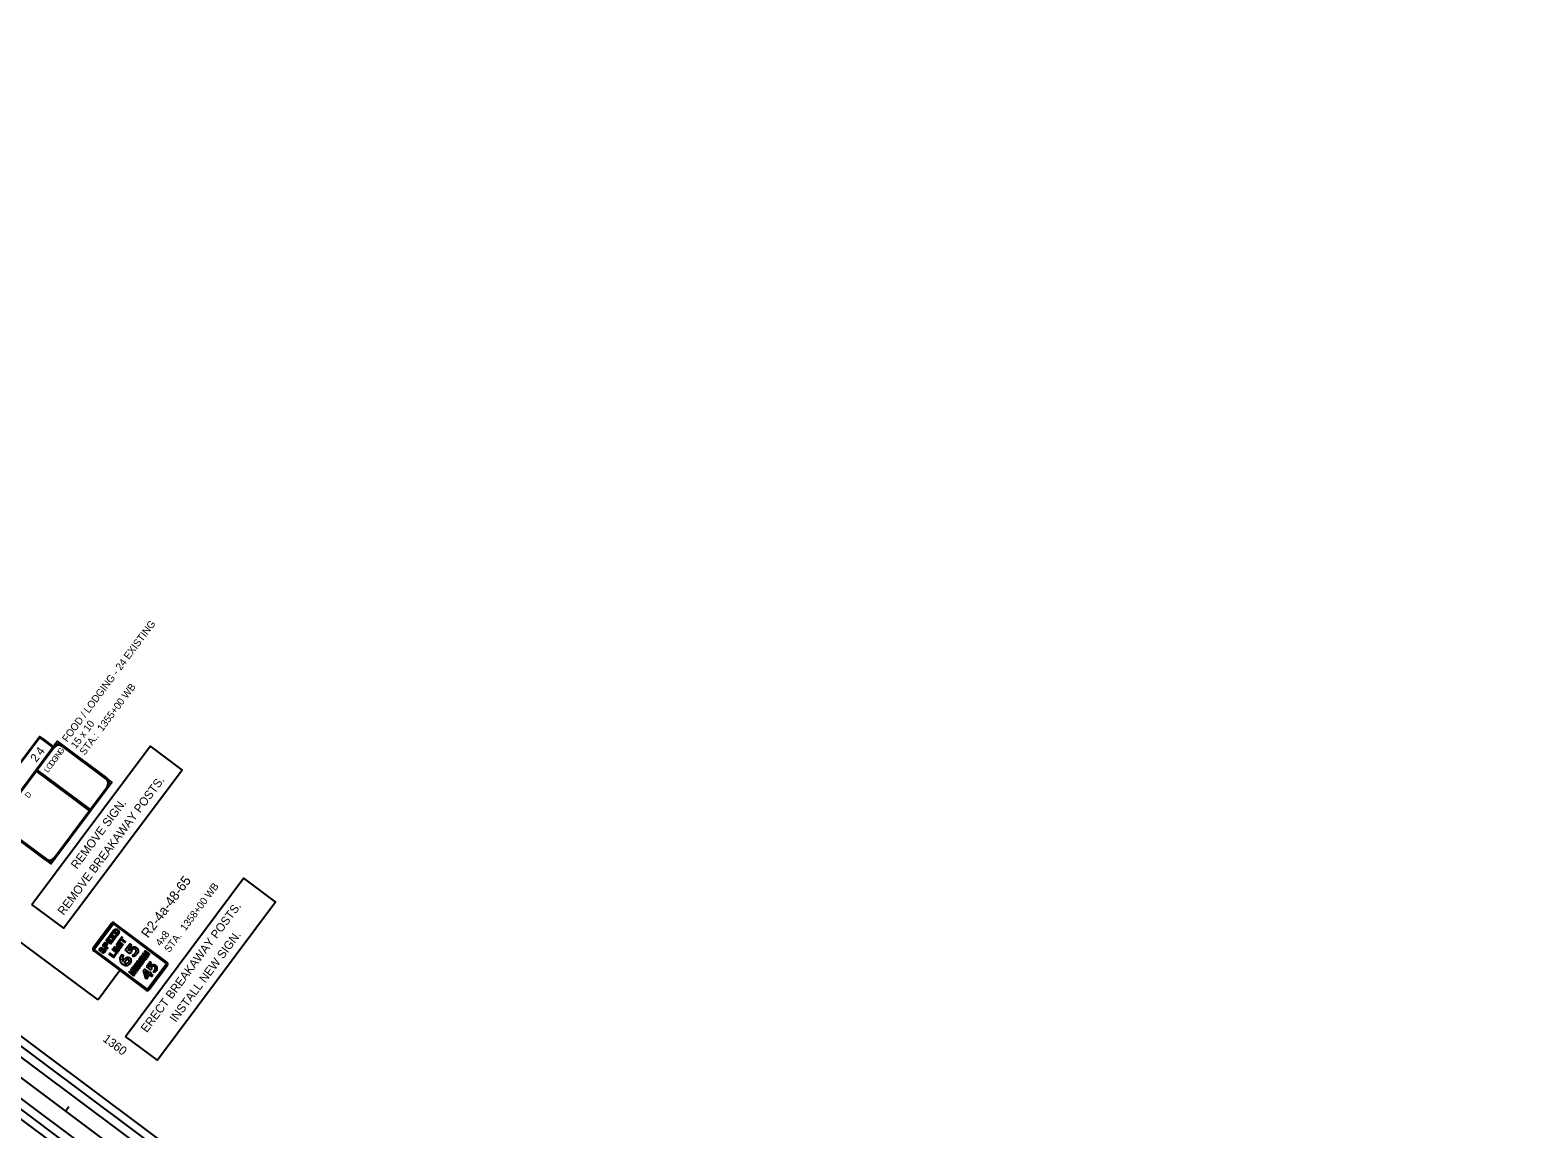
# Model space of a CAD drawing. Extents: x 2338610 to 2351914, y 366540 to 376484.
# Drawn here: x 2343223 to 2345299, y 372032 to 373544 of the extents above; entities that cross this region are included whole.
import ezdxf

# ---------------------------------------------------------------- set-up
doc = ezdxf.new("R2010")
doc.units = 0
for name, color, linetype in [('RD_HC_Cl', 7, 'Continuous'), ('RD_PD_Final_LnLine', 7, 'Continuous'), ('RD_PD_Final_TrvlWay', 7, 'Continuous'), ('TR PM PAVEMENT MARKING NOTES', 7, 'Continuous'), ('TR PM UNASSIGNED 3', 7, 'Continuous'), ('TR SN EXISTING - BREAK-AWAY SIGN SUPPORTS', 7, 'Continuous'), ('TR SN EXTRUDED PANEL SIGNS - GROUND MOUNTED', 7, 'Continuous'), ('TR SN FLAT SHEET - TYPE III - FIXED SZ and MSG SIGN', 7, 'Continuous'), ('TR SN UNASSIGNED 7', 7, 'Continuous')]:
    doc.layers.add(name, color=color, linetype=linetype)

msp = doc.modelspace()

# ---------------------------------------------------------------- linework, layer by layer
at = {"layer": 'RD_HC_Cl'}
msp.add_line((2339299.7, 375020.3), (2345298.7, 370542.8), dxfattribs=at)
at = {"layer": 'RD_PD_Final_LnLine'}
for p, q in [((2343504.5, 371925.7), (2339320.6, 375048.4)), ((2343497.3, 371916.1), (2339313.4, 375038.8)), ((2339278.7, 374992.3), (2343462.6, 371869.6)), ((2339285.9, 375001.9), (2343469.8, 371879.2))]:
    msp.add_line(p, q, dxfattribs=at)
at = {"layer": 'RD_PD_Final_TrvlWay'}
for p, q in [((2343458.6, 371973.7), (2339327.2, 375057.2)), ((2339272.2, 374983.5), (2343456.1, 371860.8))]:
    msp.add_line(p, q, dxfattribs=at)
at = {"layer": 'TR PM PAVEMENT MARKING NOTES'}
for p, q in [((2343334.7, 372314.4), (2343309.6, 372280.7)), ((2343335.3, 372313.9), (2343336.3, 372313.2)), ((2343337.7, 372313.4), (2343338.4, 372314.4)), ((2343411, 372261.2), (2343338.9, 372315)), ((2343311.2, 372279.5), (2343310.2, 372280.3)), ((2343310.2, 372276.5), (2343382.3, 372222.7)), ((2343310.6, 372277.1), (2343311.4, 372278.1)), ((2343386.5, 372223.3), (2343411.6, 372257)), ((2343410.6, 372260.5), (2343409.8, 372259.5)), ((2343410, 372258.1), (2343411, 372257.4)), ((2343383.5, 372224.3), (2343382.8, 372223.3)), ((2343385.9, 372223.7), (2343384.9, 372224.5))]:
    msp.add_line(p, q, dxfattribs=at)
for points in [[(2343335.3, 372313.9), (2343310.2, 372280.3), (2343311.2, 372279.5), (2343336.3, 372313.2), (2343335.3, 372313.9)], [(2343410.6, 372260.5), (2343338.4, 372314.4), (2343337.7, 372313.4), (2343409.8, 372259.5), (2343410.6, 372260.5)], [(2343310.6, 372277.1), (2343382.8, 372223.3), (2343383.5, 372224.3), (2343311.4, 372278.1), (2343310.6, 372277.1)], [(2343385.9, 372223.7), (2343411, 372257.4), (2343410, 372258.1), (2343384.9, 372224.5), (2343385.9, 372223.7)]]:
    msp.add_lwpolyline(points, close=True, dxfattribs=at)
for points in [[(2343322.1, 372284.2), (2343324.5, 372287.3)], [(2343325.6, 372286.5), (2343324, 372284.4)], [(2343337.3, 372291.1), (2343333.8, 372286.4), (2343327.4, 372291.2), (2343330.8, 372295.8), (2343331.9, 372295), (2343329.3, 372291.5), (2343330.6, 372290.5), (2343332, 372292.4), (2343333.1, 372291.6), (2343331.7, 372289.7), (2343333.5, 372288.3), (2343336.2, 372291.9), (2343337.3, 372291.1)], [(2343341.8, 372297.2), (2343338.3, 372292.5), (2343331.9, 372297.2), (2343335.3, 372301.9), (2343336.4, 372301), (2343333.8, 372297.5), (2343335.1, 372296.6), (2343336.5, 372298.5), (2343337.6, 372297.6), (2343336.2, 372295.7), (2343338, 372294.4), (2343340.7, 372298), (2343341.8, 372297.2)], [(2343336.3, 372303.1), (2343337.8, 372305.2)], [(2343344.2, 372300.4), (2343342.7, 372298.3), (2343336.3, 372303.1)], [(2343348.8, 372282.3), (2343348, 372281.2), (2343344.1, 372284.1), (2343346.6, 372279.3), (2343341.3, 372280.4), (2343345.2, 372277.4), (2343344.4, 372276.3), (2343338, 372281.1), (2343338.8, 372282.3), (2343344, 372281.2), (2343341.5, 372285.9), (2343342.4, 372287), (2343348.8, 372282.3)], [(2343338.9, 372304.4), (2343338.2, 372303.4)], [(2343338.2, 372303.4), (2343342.4, 372300.3), (2343343.1, 372301.2)], [(2343350.8, 372285), (2343350, 372283.9), (2343343.6, 372288.7), (2343344.4, 372289.8), (2343350.8, 372285)], [(2343349.9, 372295.1), (2343348.6, 372293.3), (2343354, 372289.2), (2343353.2, 372288.1), (2343347.8, 372292.2), (2343346.4, 372290.4), (2343345.4, 372291.1), (2343348.9, 372295.8), (2343349.9, 372295.1)], [(2343353.6, 372277.9), (2343359.9, 372286.3), (2343362.1, 372284.6), (2343357.4, 372278.3), (2343359.3, 372276.6)], [(2343320.8, 372277.5), (2343322.4, 372279)], [(2343321.5, 372281.5), (2343321.7, 372280.1)], [(2343323.3, 372278), (2343321.7, 372276.5)], [(2343328.4, 372284.4), (2343326.9, 372282.3), (2343329.4, 372280.5), (2343328.5, 372279.4), (2343322.1, 372284.2)], [(2343322.3, 372273.4), (2343322.3, 372274.8)], [(2343324, 372284.4), (2343325.8, 372283.2), (2343327.3, 372285.2)], [(2343341.3, 372272.3), (2343337.8, 372267.6), (2343331.4, 372272.3), (2343332.2, 372273.4), (2343337.6, 372269.4), (2343340.3, 372273), (2343341.3, 372272.3)], [(2343343.1, 372274.7), (2343342.3, 372273.6), (2343335.9, 372278.4), (2343336.7, 372279.5), (2343343.1, 372274.7)], [(2343348.7, 372271.3), (2343349.2, 372272)], [(2343349.2, 372272), (2343351.4, 372270.3), (2343351, 372269.7)], [(2343361.6, 372274.6), (2343359.3, 372273), (2343353.6, 372277.9)], [(2343364.8, 372268.3), (2343363.5, 372270.7)], [(2343379.5, 372261.5), (2343378.8, 372260.6), (2343375.2, 372263.3), (2343377.9, 372259.4), (2343373.4, 372260.9), (2343377, 372258.2), (2343376.4, 372257.3), (2343369.9, 372262.1), (2343370.6, 372263.1), (2343375, 372261.6), (2343372.4, 372265.4), (2343373, 372266.3), (2343379.5, 372261.5)], [(2343378.8, 372264.1), (2343374, 372267.6), (2343374.7, 372268.5), (2343379.5, 372265)], [(2343380.8, 372266.7), (2343376, 372270.2), (2343376.7, 372271.1)], [(2343376.7, 372271.1), (2343381.4, 372267.6)], [(2343387.2, 372271.9), (2343386.5, 372271), (2343382.9, 372273.7), (2343385.6, 372269.8), (2343381.2, 372271.3), (2343384.8, 372268.6), (2343384.1, 372267.7), (2343377.7, 372272.5), (2343378.4, 372273.4), (2343382.7, 372272), (2343380.1, 372275.7), (2343380.8, 372276.7), (2343387.2, 372271.9)], [(2343368.4, 372246.6), (2343367.7, 372245.7), (2343364.1, 372248.4), (2343366.8, 372244.6), (2343362.3, 372246.1), (2343365.9, 372243.4), (2343365.3, 372242.5), (2343358.8, 372247.3), (2343359.5, 372248.2), (2343363.9, 372246.7), (2343361.3, 372250.5), (2343361.9, 372251.4), (2343368.4, 372246.6)], [(2343370, 372248.9), (2343369.4, 372248), (2343363, 372252.8), (2343363.6, 372253.7), (2343370, 372248.9)], [(2343373.7, 372253.7), (2343373.1, 372253), (2343367.5, 372254.3), (2343371.7, 372251.1), (2343371, 372250.2), (2343364.6, 372255), (2343365.3, 372255.9), (2343370.3, 372254.8), (2343366.6, 372257.6), (2343367.3, 372258.5), (2343373.7, 372253.7)], [(2343375.3, 372256), (2343374.7, 372255.1), (2343368.3, 372259.9), (2343368.9, 372260.8), (2343375.3, 372256)], [(2343389.3, 372246.3), (2343388.5, 372245.3), (2343391.3, 372243.2), (2343390, 372241.4), (2343387.2, 372243.5), (2343383.2, 372238.1), (2343382.1, 372238.8), (2343378.8, 372249.8), (2343380.1, 372251.5), (2343387, 372246.4), (2343387.7, 372247.5), (2343389.3, 372246.3)], [(2343385.7, 372244.7), (2343381.5, 372247.8), (2343383.4, 372241.6), (2343385.7, 372244.7)], [(2343382.9, 372255.2), (2343387.6, 372261.6), (2343389.4, 372260.3), (2343385.9, 372255.6), (2343387.8, 372254)], [(2343390.2, 372251.9), (2343388.5, 372250.6), (2343382.9, 372255.2)], [(2343393.3, 372246.6), (2343392.3, 372248.5)]]:
    msp.add_lwpolyline(points, dxfattribs=at)
for centre, radius, start, end in [((2343337.1, 372312.6), 3, 53.2637, 143.2639), ((2343337.1, 372312.6), 2.25, 53.2637, 143.2639), ((2343337.1, 372312.6), 1, 53.2637, 143.2639), ((2343312, 372278.9), 3, 143.2639, 233.2636), ((2343312, 372278.9), 2.25, 143.2639, 233.2636), ((2343312, 372278.9), 1, 143.2639, 233.2636), ((2343409.2, 372258.7), 1, 323.2638, 53.264), ((2343409.2, 372258.7), 2.25, 323.2638, 53.264), ((2343409.2, 372258.7), 3, 323.2638, 53.264), ((2343384.1, 372225.1), 3, 233.2636, 323.2638), ((2343384.1, 372225.1), 2.25, 233.2636, 323.2638), ((2343384.1, 372225.1), 1, 233.2636, 323.2638)]:
    msp.add_arc(centre, radius, start, end, dxfattribs=at)
for points in [[(2343337.8, 372305.2), (2343338.7, 372306.3), (2343340.1, 372306.6), (2343341.5, 372306.9), (2343342.7, 372306.2), (2343343, 372306), (2343343.3, 372305.8), (2343343.6, 372305.6), (2343343.9, 372305.3), (2343344.9, 372304.3), (2343345, 372302.9), (2343345.1, 372301.5), (2343344.2, 372300.4)], [(2343324.5, 372287.3), (2343325.1, 372288.1), (2343326.1, 372288.3), (2343327.1, 372288.4), (2343327.9, 372287.8), (2343328.7, 372287.2), (2343328.8, 372286.2), (2343329, 372285.2), (2343328.4, 372284.4)], [(2343327.3, 372285.2), (2343327.5, 372285.6), (2343327.5, 372286), (2343327.4, 372286.4), (2343327.1, 372286.7), (2343326.7, 372287), (2343326.3, 372286.9), (2343325.8, 372286.8), (2343325.6, 372286.5)], [(2343343.1, 372301.2), (2343343.7, 372302), (2343343.6, 372302.9), (2343343.5, 372303.7), (2343342.9, 372304.4), (2343342.7, 372304.5), (2343342.5, 372304.7), (2343342.2, 372304.9), (2343342, 372305), (2343341.2, 372305.5), (2343340.3, 372305.3), (2343339.5, 372305.1), (2343338.9, 372304.4)], [(2343321.7, 372276.5), (2343321.1, 372276), (2343320.4, 372276), (2343319.6, 372275.9), (2343319, 372276.4), (2343318.5, 372276.8), (2343318.3, 372277.3), (2343318, 372277.9), (2343318.2, 372278.5), (2343318.4, 372279.3), (2343318.8, 372280), (2343319.8, 372281.3), (2343321.5, 372281.5)], [(2343321.7, 372280.1), (2343320.6, 372280), (2343319.9, 372279.2), (2343319.6, 372278.7), (2343319.5, 372278.3), (2343319.4, 372277.8), (2343319.8, 372277.5), (2343320, 372277.3), (2343320.3, 372277.3), (2343320.6, 372277.3), (2343320.8, 372277.5)], [(2343322.4, 372279), (2343323, 372279.5), (2343323.8, 372279.6), (2343324.6, 372279.6), (2343325.3, 372279.1), (2343326.4, 372278.3), (2343326.2, 372277), (2343326.1, 372275.9), (2343325.5, 372275), (2343324.9, 372274.3), (2343324, 372273.8), (2343323.2, 372273.4), (2343322.3, 372273.4)], [(2343322.3, 372274.8), (2343323.6, 372274.8), (2343324.4, 372275.9), (2343324.8, 372276.5), (2343324.9, 372277.2), (2343324.9, 372277.7), (2343324.5, 372278), (2343324.2, 372278.2), (2343323.9, 372278.2), (2343323.5, 372278.2), (2343323.3, 372278)], [(2343351, 372269.7), (2343349.6, 372267.9), (2343349.6, 372265.8), (2343349.5, 372263.6), (2343350.6, 372261.8), (2343351.1, 372263.4), (2343352.1, 372264.8), (2343353.1, 372266.1), (2343354.5, 372267), (2343355.7, 372267.8), (2343357.1, 372267.8), (2343358.6, 372267.8), (2343359.7, 372266.9), (2343360.9, 372266), (2343361.3, 372264.7), (2343361.7, 372263.3), (2343361.3, 372262), (2343360.9, 372260.4), (2343359.8, 372259), (2343358.8, 372257.7), (2343357.5, 372256.8), (2343355.7, 372255.6), (2343353.6, 372256.2), (2343352.1, 372256.7), (2343350.7, 372257.7), (2343347.5, 372260.1), (2343346.9, 372264.1), (2343346.3, 372268.1), (2343348.7, 372271.3)], [(2343358.1, 372264.7), (2343357.1, 372265.5), (2343356, 372264.7), (2343355, 372264), (2343354.3, 372263.1), (2343353.6, 372262.2), (2343353.3, 372261), (2343352.9, 372259.9), (2343353.9, 372259.1), (2343354.9, 372258.4), (2343356, 372259.1), (2343356.9, 372259.7), (2343357.6, 372260.7), (2343358.3, 372261.6), (2343358.7, 372262.8), (2343359.1, 372264), (2343358.1, 372264.7)], [(2343359.3, 372276.6), (2343359.9, 372278.4), (2343361, 372279.8), (2343362.4, 372281.7), (2343364.8, 372282.1), (2343367.2, 372282.4), (2343369.1, 372281), (2343371, 372279.6), (2343371.3, 372277.2), (2343371.6, 372274.9), (2343370.2, 372272.9), (2343368, 372270), (2343364.8, 372268.3)], [(2343363.5, 372270.7), (2343366.2, 372272.1), (2343368, 372274.6), (2343368.8, 372275.6), (2343368.6, 372276.8), (2343368.4, 372278.1), (2343367.4, 372278.8), (2343366.4, 372279.5), (2343365.2, 372279.4), (2343364, 372279.2), (2343363.2, 372278.2), (2343362, 372276.6), (2343361.6, 372274.6)], [(2343381.4, 372267.6), (2343382.2, 372267.1), (2343382.3, 372266.2), (2343382.4, 372265.3), (2343381.9, 372264.5), (2343381.3, 372263.8), (2343380.4, 372263.7), (2343379.5, 372263.5), (2343378.8, 372264.1)], [(2343379.5, 372265), (2343379.8, 372264.7), (2343380.3, 372264.8), (2343380.7, 372264.8), (2343381, 372265.2), (2343381.2, 372265.6), (2343381.2, 372266), (2343381.1, 372266.4), (2343380.8, 372266.7)], [(2343387.8, 372254), (2343388, 372255.1), (2343388.6, 372256), (2343389.8, 372257.5), (2343391.7, 372257.8), (2343393.6, 372258.1), (2343395.2, 372256.9), (2343397.1, 372255.5), (2343397.1, 372252.9), (2343397.2, 372250.6), (2343395.7, 372248.6), (2343394.7, 372247.3), (2343393.3, 372246.6)], [(2343392.3, 372248.5), (2343393.3, 372249), (2343393.9, 372249.9), (2343394.8, 372251.1), (2343394.9, 372252.6), (2343395, 372254.3), (2343393.9, 372255.2), (2343393.1, 372255.8), (2343392, 372255.7), (2343391, 372255.5), (2343390.4, 372254.7), (2343389.9, 372254.1), (2343389.9, 372253.3), (2343389.8, 372252.5), (2343390.2, 372251.9)]]:
    msp.add_open_spline(points, degree=3, dxfattribs=at)
at = {"layer": 'TR SN EXISTING - BREAK-AWAY SIGN SUPPORTS'}
for points in [[(2343225.1, 372340.5), (2343387.8, 372558.5), (2343431.8, 372525.6), (2343269.1, 372307.7)], [(2343353.8, 372158.8), (2343516.5, 372376.8), (2343560.5, 372343.9), (2343397.8, 372126)]]:
    msp.add_lwpolyline(points, close=True, dxfattribs=at)
at = {"layer": 'TR SN EXTRUDED PANEL SIGNS - GROUND MOUNTED'}
for p, q in [((2343233, 372567.9), (2343233.6, 372567.4)), ((2343239.1, 372568.2), (2343239.6, 372568.9)), ((2343254.6, 372557.6), (2343255.8, 372556.7)), ((2343266.8, 372558.3), (2343267.7, 372559.5)), ((2343327.8, 372514.7), (2343326.9, 372513.4)), ((2343328.5, 372502.5), (2343329.7, 372501.6)), ((2343244.6, 372403.2), (2343243.7, 372402)), ((2343256.8, 372403.9), (2343255.6, 372404.8)), ((2343316.1, 372209.2), (2343200.4, 372295.6)), ((2343346.2, 372249.6), (2343316.1, 372209.2))]:
    msp.add_line(p, q, dxfattribs=at)
for points in [[(2343209.7, 372497.5), (2343254.6, 372557.6), (2343235.8, 372571.7), (2343190.9, 372511.6), (2343209.7, 372497.5), (2343209.7, 372497.5)], [(2343233.6, 372567.4), (2343194.4, 372514.8), (2343193.8, 372515.3), (2343233, 372567.9), (2343233.6, 372567.4), (2343233.6, 372567.4)], [(2343305.4, 372469), (2343335.3, 372509.1), (2343260.2, 372565.2), (2343230.3, 372525.1), (2343305.4, 372469), (2343305.4, 372469)], [(2343255.8, 372556.7), (2343232.5, 372525.4), (2343231.2, 372526.3), (2343254.6, 372557.6), (2343255.8, 372556.7), (2343255.8, 372556.7)], [(2343254.1, 372557), (2343239.1, 372568.2), (2343239.6, 372568.9), (2343254.6, 372557.6), (2343254.1, 372557), (2343254.1, 372557)], [(2343326.9, 372513.4), (2343266.8, 372558.3), (2343267.7, 372559.5), (2343327.8, 372514.7), (2343326.9, 372513.4), (2343326.9, 372513.4)], [(2343251.2, 372396.4), (2343305.4, 372469), (2343230.3, 372525.1), (2343176.1, 372452.5), (2343251.2, 372396.4), (2343251.2, 372396.4)], [(2343231.5, 372524.2), (2343182.9, 372459), (2343181.7, 372460), (2343230.3, 372525.1), (2343231.5, 372524.2), (2343231.5, 372524.2)], [(2343231.2, 372526.3), (2343232.5, 372525.4), (2343231.5, 372524.2), (2343230.3, 372525.1), (2343231.2, 372526.3), (2343231.2, 372526.3)], [(2343232.5, 372525.4), (2343305.1, 372471.2), (2343304.2, 372469.9), (2343231.5, 372524.2), (2343232.5, 372525.4), (2343232.5, 372525.4)], [(2343305.1, 372471.2), (2343328.5, 372502.5), (2343329.7, 372501.6), (2343306.4, 372470.3), (2343305.1, 372471.2), (2343305.1, 372471.2)], [(2343255.6, 372404.8), (2343304.2, 372469.9), (2343305.4, 372469), (2343256.8, 372403.9), (2343255.6, 372404.8), (2343255.6, 372404.8)], [(2343304.2, 372469.9), (2343305.1, 372471.2), (2343306.4, 372470.3), (2343305.4, 372469), (2343304.2, 372469.9), (2343304.2, 372469.9)], [(2343184.5, 372448.1), (2343244.6, 372403.2), (2343243.7, 372402), (2343183.6, 372446.9), (2343184.5, 372448.1), (2343184.5, 372448.1)]]:
    msp.add_lwpolyline(points, close=True, dxfattribs=at)
for centre, radius, start, end in [((2343236.8, 372565.1), 4.69, 53.2637, 143.2639), ((2343236.8, 372565.1), 3.91, 53.2637, 143.2639), ((2343262.1, 372552), 9.38, 53.2637, 143.2639), ((2343262.1, 372552), 7.81, 53.2637, 143.2639), ((2343322.2, 372507.2), 9.38, 323.2638, 53.264), ((2343322.2, 372507.2), 7.81, 323.2638, 53.264), ((2343249.3, 372409.5), 9.38, 233.2636, 323.2638), ((2343249.3, 372409.5), 7.81, 233.2636, 323.2638)]:
    msp.add_arc(centre, radius, start, end, dxfattribs=at)
at = {"layer": 'TR SN UNASSIGNED 7'}
msp.add_line((2343271.2, 372056.1), (2343276, 372062.5), dxfattribs=at)

# ---------------------------------------------------------------- texts
at = {"layer": 'TR PM UNASSIGNED 3'}
for s, p in [('FOOD / LODGING - 24 EXISTING', (2343273.7, 372563.3)), ('STA.:  1355+00 WB', (2343297.8, 372545.3)), ('15 x 10', (2343285.7, 372554.3)), ('STA.  1358+00 WB', (2343414.3, 372273.6)), ('4x8', (2343402.3, 372282.6))]:
    msp.add_text(s, height=10, rotation=53.2637, dxfattribs=at).set_placement(p)
at = {"layer": 'TR SN EXISTING - BREAK-AWAY SIGN SUPPORTS'}
for s, p in [('REMOVE BREAKAWAY POSTS.', (2343268.8, 372324.8)), ('REMOVE SIGN.', (2343287.1, 372388.4)), ('ERECT BREAKAWAY POSTS.', (2343383.3, 372163.3)), ('INSTALL NEW SIGN.', (2343423.1, 372177.4))]:
    msp.add_text(s, height=11.719, rotation=53.2638, dxfattribs=at).set_placement(p)
at = {"layer": 'TR SN EXTRUDED PANEL SIGNS - GROUND MOUNTED'}
for s, height, p in [('4', 11.7, (2343238.3, 372544.9)), ('G', 7.81, (2343265.9, 372546.7)), ('2', 11.7, (2343231.2, 372535.5)), ('O', 7.81, (2343250.2, 372525.6)), ('D', 7.81, (2343253.9, 372530.5)), ('G', 7.81, (2343257.2, 372535)), ('I', 7.81, (2343260.7, 372539.8)), ('N', 7.81, (2343262.4, 372542)), ('L', 7.81, (2343247.1, 372521.4)), ('D', 7.81, (2343220.7, 372486.2))]:
    msp.add_text(s, height=height, rotation=53.2637, dxfattribs=at).set_placement(p)
at = {"layer": 'TR SN FLAT SHEET - TYPE III - FIXED SZ and MSG SIGN'}
msp.add_text('R2-4a-48-65', height=13.333, rotation=53.2637, dxfattribs=at).set_placement((2343385.1, 372293.3))
at = {"layer": 'TR SN UNASSIGNED 7'}
msp.add_text('1360', height=12, rotation=323.2637, dxfattribs=at).set_placement((2343321.6, 372153.3))

doc.saveas('drawing.dxf')
